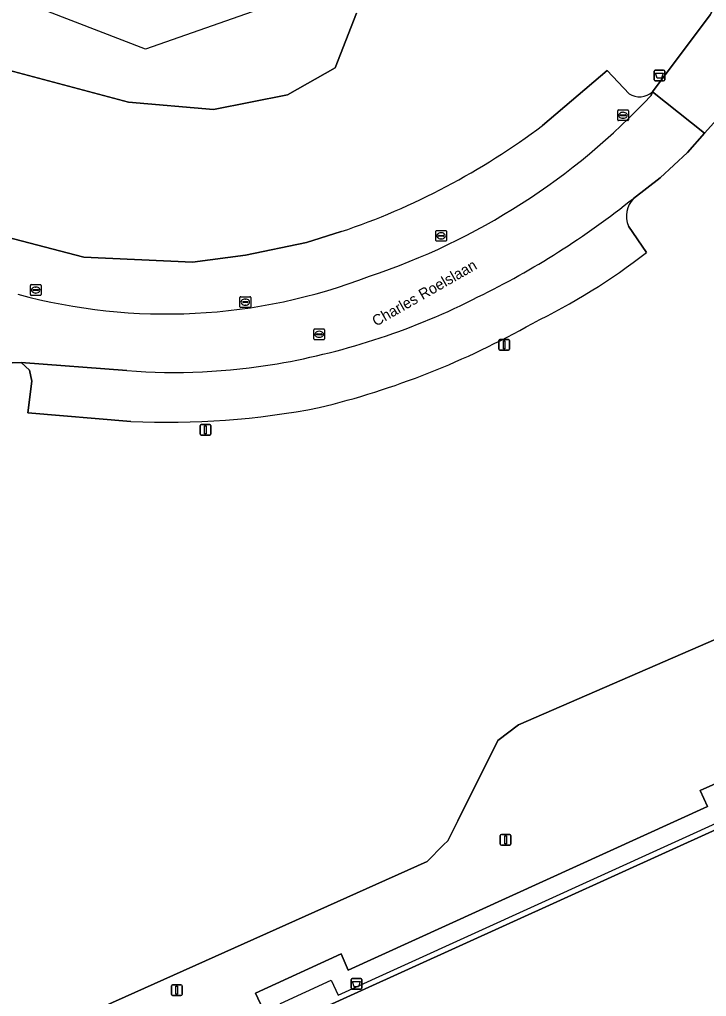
# Model space of a CAD drawing. Extents: x 161090 to 161692, y 379509 to 380907.
# Drawn here: x 161218.4 to 161282.3, y 380030.3 to 380121.1 of the extents above; entities that cross this region are included whole.
import ezdxf

# ---------------------------------------------------------------- set-up
doc = ezdxf.new("R2010")
doc.units = 0
for name, color, linetype in [('IMGEO_Afvalbak', 7, 'Continuous'), ('IMGEO_Groenvoorziening', 7, 'Continuous'), ('IMGEO_Hek', 7, 'Continuous'), ('IMGEO_Kolk', 7, 'Continuous'), ('IMGEO_Lichtmast', 7, 'Continuous'), ('IMGEO_Loofbos', 7, 'Continuous'), ('IMGEO_Openbare_ruimte_label', 7, 'Continuous'), ('IMGEO_Parkeervlak_gesloten', 7, 'Continuous'), ('IMGEO_Rijbaan_lokaal_gesloten', 7, 'Continuous'), ('IMGEO_Rioolput', 7, 'Continuous'), ('IMGEO_Terreindeel_open', 7, 'Continuous'), ('IMGEO_Voetpad_open', 7, 'Continuous'), ('IMGEO_Waterloop', 7, 'Continuous')]:
    doc.layers.add(name, color=color, linetype=linetype)

msp = doc.modelspace()

# ---------------------------------------------------------------- linework, layer by layer
at = {"layer": 'IMGEO_Afvalbak'}
for p, q in [((161277.425, 380115.546), (161277.425, 380116.346)), ((161277.425, 380116.346), (161277.425, 380115.546)), ((161277.525, 380116.446), (161278.315, 380116.446)), ((161278.315, 380116.446), (161277.525, 380116.446)), ((161278.415, 380116.346), (161278.415, 380115.546)), ((161278.415, 380115.546), (161278.415, 380116.346)), ((161278.315, 380115.446), (161277.525, 380115.446)), ((161277.525, 380115.446), (161278.315, 380115.446)), ((161249.255, 380031.115), (161249.255, 380031.915)), ((161249.255, 380031.915), (161249.255, 380031.115)), ((161249.355, 380032.015), (161250.145, 380032.015)), ((161250.145, 380032.015), (161249.355, 380032.015)), ((161250.245, 380031.915), (161250.245, 380031.115)), ((161250.245, 380031.115), (161250.245, 380031.915)), ((161250.145, 380031.015), (161249.355, 380031.015)), ((161249.355, 380031.015), (161250.145, 380031.015))]:
    msp.add_line(p, q, dxfattribs=at)
for points in [[(161277.568, 380116.16), (161278.272, 380116.16), (161278.123, 380115.69), (161277.717, 380115.69), (161277.568, 380116.16)], [(161249.398, 380031.729), (161250.102, 380031.729), (161249.953, 380031.259), (161249.547, 380031.259), (161249.398, 380031.729)]]:
    msp.add_lwpolyline(points, dxfattribs=at)
for centre, start, end in [((161277.525, 380116.346), 90, 180), ((161277.525, 380116.346), 90, 180), ((161278.315, 380116.346), 0, 90), ((161278.315, 380116.346), 360, 90), ((161277.525, 380115.546), 180, 270), ((161277.525, 380115.546), 180, 270), ((161278.315, 380115.546), 270, 0), ((161278.315, 380115.546), 270, 0), ((161249.355, 380031.915), 90, 180), ((161249.355, 380031.915), 90, 180), ((161250.145, 380031.915), 0, 90), ((161250.145, 380031.915), 360, 90), ((161249.355, 380031.115), 180, 270), ((161249.355, 380031.115), 180, 270), ((161250.145, 380031.115), 270, 0), ((161250.145, 380031.115), 270, 0)]:
    msp.add_arc(centre, 0.1, start, end, dxfattribs=at)
at = {"layer": 'IMGEO_Groenvoorziening'}
msp.add_lwpolyline([(161305.516, 380073.263), (161264.808, 380055.587), (161262.89, 380054.125), (161259.172, 380046.687), (161258.233, 380044.807), (161257.86, 380044.434), (161256.315, 380042.888), (161212.115, 380023.104), (161244.332, 379950.948), (161248.71, 379952.968), (161248.207, 379953.948), (161218.695, 380019.077), (161223.462, 380021.221), (161230.069, 380024.187), (161241.037, 380029.206), (161240.363, 380030.654), (161248.318, 380034.301), (161248.967, 380032.793), (161282.396, 380047.991), (161281.717, 380049.48), (161289.948, 380053.183)], dxfattribs=at)
at = {"layer": 'IMGEO_Hek'}
msp.add_lwpolyline([(161282.49, 379981.114), (161272.326, 379976.507), (161272.946, 379975.155), (161268.403, 379973.073), (161267.745, 379974.424), (161245.458, 379964.327), (161243.588, 379968.636), (161221.01, 380018.226), (161243.313, 380028.348), (161242.697, 380029.7), (161247.399, 380031.857), (161248.045, 380030.463), (161284.892, 380047.225), (161284.302, 380048.589), (161288.939, 380050.72), (161289.598, 380049.351), (161311.663, 380059.359), (161336.159, 380005.46), (161313.894, 379995.295), (161314.507, 379993.981), (161309.839, 379991.856), (161309.202, 379993.224), (161299.077, 379988.609)], dxfattribs=at)
at = {"layer": 'IMGEO_Kolk'}
for p, q in [((161274.042, 380111.822), (161274.042, 380112.674)), ((161274.117, 380112.748), (161274.969, 380112.748)), ((161274.344, 380112.291), (161274.742, 380112.291)), ((161274.53, 380112.528), (161274.555, 380112.528)), ((161275.043, 380112.674), (161275.043, 380111.822)), ((161274.969, 380111.748), (161274.117, 380111.748)), ((161274.301, 380112.242), (161274.301, 380112.254)), ((161274.739, 380112.205), (161274.341, 380112.205)), ((161274.553, 380111.968), (161274.528, 380111.968)), ((161274.785, 380112.254), (161274.785, 380112.242)), ((161257.126, 380100.616), (161257.126, 380101.468)), ((161257.201, 380101.542), (161258.053, 380101.542)), ((161258.127, 380101.468), (161258.127, 380100.616)), ((161258.053, 380100.542), (161257.201, 380100.542)), ((161257.385, 380101.036), (161257.385, 380101.048)), ((161257.823, 380100.999), (161257.425, 380100.999)), ((161257.428, 380101.085), (161257.826, 380101.085)), ((161257.637, 380100.762), (161257.612, 380100.762)), ((161257.614, 380101.322), (161257.639, 380101.322)), ((161257.869, 380101.048), (161257.869, 380101.036)), ((161219.439, 380095.581), (161219.439, 380096.433)), ((161219.514, 380096.507), (161220.366, 380096.507)), ((161219.698, 380096.001), (161219.698, 380096.013)), ((161220.136, 380095.964), (161219.738, 380095.964)), ((161219.741, 380096.05), (161220.139, 380096.05)), ((161219.927, 380096.287), (161219.952, 380096.287)), ((161220.182, 380096.013), (161220.182, 380096.001)), ((161220.44, 380096.433), (161220.44, 380095.581)), ((161220.366, 380095.507), (161219.514, 380095.507)), ((161219.95, 380095.727), (161219.925, 380095.727)), ((161238.918, 380094.458), (161238.918, 380095.31)), ((161238.993, 380095.384), (161239.845, 380095.384)), ((161239.406, 380095.164), (161239.431, 380095.164)), ((161239.919, 380095.31), (161239.919, 380094.458)), ((161239.845, 380094.384), (161238.993, 380094.384)), ((161239.177, 380094.878), (161239.177, 380094.89)), ((161239.615, 380094.841), (161239.217, 380094.841)), ((161239.22, 380094.927), (161239.618, 380094.927)), ((161239.429, 380094.604), (161239.404, 380094.604)), ((161239.661, 380094.89), (161239.661, 380094.878))]:
    msp.add_line(p, q, dxfattribs=at)
for points in [[(161274.042, 380111.822), (161274.042, 380112.674)], [(161274.117, 380112.748), (161274.969, 380112.748)], [(161275.043, 380112.674), (161275.043, 380111.822)], [(161274.969, 380111.748), (161274.117, 380111.748)], [(161257.126, 380100.616), (161257.126, 380101.468)], [(161257.201, 380101.542), (161258.053, 380101.542)], [(161258.127, 380101.468), (161258.127, 380100.616)], [(161258.053, 380100.542), (161257.201, 380100.542)], [(161219.439, 380095.581), (161219.439, 380096.433)], [(161219.514, 380096.507), (161220.366, 380096.507)], [(161220.44, 380096.433), (161220.44, 380095.581)], [(161220.366, 380095.507), (161219.514, 380095.507)], [(161238.918, 380094.458), (161238.918, 380095.31)], [(161238.993, 380095.384), (161239.845, 380095.384)], [(161239.919, 380095.31), (161239.919, 380094.458)], [(161239.845, 380094.384), (161238.993, 380094.384)]]:
    msp.add_lwpolyline(points, dxfattribs=at)
for centre, radius, start, end in [((161274.119, 380112.672), 0.0765, 91.55205, 178.44795), ((161274.119, 380112.672), 0.0765, 91.55205, 178.44795), ((161274.341, 380112.251), 0.0403, 85.87752, 175.75265), ((161274.746, 380112.253), 0.0386, 1.73085, 96.63898), ((161274.967, 380112.672), 0.0765, 1.55205, 88.44795), ((161274.967, 380112.672), 0.0765, 1.55205, 88.44795), ((161274.119, 380111.824), 0.0765, 181.55205, 268.44795), ((161274.119, 380111.824), 0.0765, 181.55205, 268.44795), ((161274.338, 380112.241), 0.0366, 178.93798, 274.71019), ((161274.742, 380112.248), 0.043, 264.86636, 352.45326), ((161274.967, 380111.824), 0.0765, 271.55205, 358.44795), ((161274.967, 380111.824), 0.0765, 271.55205, 358.44795), ((161257.203, 380101.466), 0.0765, 91.55205, 178.44795), ((161257.203, 380101.466), 0.0765, 91.55205, 178.44795), ((161258.051, 380101.466), 0.0765, 1.55205, 88.44795), ((161258.051, 380101.466), 0.0765, 1.55205, 88.44795), ((161257.203, 380100.618), 0.0765, 181.55205, 268.44795), ((161257.203, 380100.618), 0.0765, 181.55205, 268.44795), ((161257.425, 380101.045), 0.0403, 85.87752, 175.75265), ((161257.422, 380101.035), 0.0366, 178.93798, 274.71019), ((161257.826, 380101.042), 0.043, 264.86636, 352.45326), ((161257.83, 380101.047), 0.0386, 1.73085, 96.63898), ((161258.051, 380100.618), 0.0765, 271.55205, 358.44795), ((161258.051, 380100.618), 0.0765, 271.55205, 358.44795), ((161219.516, 380096.431), 0.0765, 91.55205, 178.44795), ((161219.516, 380096.431), 0.0765, 91.55205, 178.44795), ((161219.738, 380096.01), 0.0403, 85.87752, 175.75265), ((161219.735, 380096), 0.0366, 178.93798, 274.71019), ((161220.139, 380096.007), 0.043, 264.86636, 352.45326), ((161220.143, 380096.012), 0.0386, 1.73085, 96.63898), ((161220.364, 380096.431), 0.0765, 1.55205, 88.44795), ((161220.364, 380096.431), 0.0765, 1.55205, 88.44795), ((161219.516, 380095.583), 0.0765, 181.55205, 268.44795), ((161219.516, 380095.583), 0.0765, 181.55205, 268.44795), ((161220.364, 380095.583), 0.0765, 271.55205, 358.44795), ((161220.364, 380095.583), 0.0765, 271.55205, 358.44795), ((161238.995, 380095.308), 0.0765, 91.55205, 178.44795), ((161238.995, 380095.308), 0.0765, 91.55205, 178.44795), ((161239.843, 380095.308), 0.0765, 1.55205, 88.44795), ((161239.843, 380095.308), 0.0765, 1.55205, 88.44795), ((161238.995, 380094.46), 0.0765, 181.55205, 268.44795), ((161238.995, 380094.46), 0.0765, 181.55205, 268.44795), ((161239.217, 380094.887), 0.0403, 85.87752, 175.75265), ((161239.214, 380094.877), 0.0366, 178.93798, 274.71019), ((161239.618, 380094.884), 0.043, 264.86636, 352.45326), ((161239.622, 380094.889), 0.0386, 1.73085, 96.63898), ((161239.843, 380094.46), 0.0765, 271.55205, 358.44795), ((161239.843, 380094.46), 0.0765, 271.55205, 358.44795)]:
    msp.add_arc(centre, radius, start, end, dxfattribs=at)
for centre, major_axis, ratio, start_param, end_param in [((161274.529, 380112.248), (-0.387, 0.002), 0.722429, 4.712389, 7.853982), ((161274.554, 380112.248), (-0.39, 0.002), 0.717154, 1.570796, 4.712389), ((161257.613, 380101.042), (-0.387, 0.002), 0.722429, 4.712389, 7.853982), ((161257.638, 380101.042), (-0.39, 0.002), 0.717154, 1.570796, 4.712389), ((161219.926, 380096.007), (-0.387, 0.002), 0.722429, 4.712389, 7.853982), ((161219.951, 380096.007), (-0.39, 0.002), 0.717154, 1.570796, 4.712389), ((161239.405, 380094.884), (-0.387, 0.002), 0.722429, 4.712389, 7.853982), ((161239.43, 380094.884), (-0.39, 0.002), 0.717154, 1.570796, 4.712389)]:
    msp.add_ellipse(centre, major_axis=major_axis, ratio=ratio, start_param=start_param, end_param=end_param, dxfattribs=at)
at = {"layer": 'IMGEO_Lichtmast'}
for p, q in [((161263.093, 380091.406), (161263.883, 380091.406)), ((161263.883, 380091.406), (161263.093, 380091.406)), ((161262.993, 380090.506), (161262.993, 380091.306)), ((161262.993, 380091.306), (161262.993, 380090.506)), ((161263.983, 380091.306), (161263.983, 380090.506)), ((161263.983, 380090.506), (161263.983, 380091.306)), ((161263.883, 380090.406), (161263.093, 380090.406)), ((161263.093, 380090.406), (161263.883, 380090.406)), ((161235.219, 380082.608), (161235.219, 380083.408)), ((161235.219, 380083.408), (161235.219, 380082.608)), ((161235.319, 380083.508), (161236.109, 380083.508)), ((161236.109, 380083.508), (161235.319, 380083.508)), ((161236.209, 380083.408), (161236.209, 380082.608)), ((161236.209, 380082.608), (161236.209, 380083.408)), ((161236.109, 380082.508), (161235.319, 380082.508)), ((161235.319, 380082.508), (161236.109, 380082.508)), ((161263.127, 380044.505), (161263.127, 380045.305)), ((161263.127, 380045.305), (161263.127, 380044.505)), ((161263.227, 380045.405), (161264.017, 380045.405)), ((161264.017, 380045.405), (161263.227, 380045.405)), ((161264.117, 380045.305), (161264.117, 380044.505)), ((161264.117, 380044.505), (161264.117, 380045.305)), ((161264.017, 380044.405), (161263.227, 380044.405)), ((161263.227, 380044.405), (161264.017, 380044.405)), ((161232.546, 380030.534), (161232.546, 380031.334)), ((161232.546, 380031.334), (161232.546, 380030.534)), ((161232.646, 380031.434), (161233.436, 380031.434)), ((161233.436, 380031.434), (161232.646, 380031.434)), ((161233.536, 380031.334), (161233.536, 380030.534)), ((161233.536, 380030.534), (161233.536, 380031.334)), ((161233.436, 380030.434), (161232.646, 380030.434)), ((161232.646, 380030.434), (161233.436, 380030.434))]:
    msp.add_line(p, q, dxfattribs=at)
for points in [[(161263.413, 380091.281), (161263.563, 380091.281), (161263.563, 380090.531), (161263.413, 380090.531), (161263.413, 380091.281)], [(161235.639, 380083.383), (161235.789, 380083.383), (161235.789, 380082.633), (161235.639, 380082.633), (161235.639, 380083.383)], [(161263.547, 380045.28), (161263.697, 380045.28), (161263.697, 380044.53), (161263.547, 380044.53), (161263.547, 380045.28)], [(161232.966, 380031.309), (161233.116, 380031.309), (161233.116, 380030.559), (161232.966, 380030.559), (161232.966, 380031.309)]]:
    msp.add_lwpolyline(points, dxfattribs=at)
for centre, start, end in [((161263.093, 380091.306), 90, 180), ((161263.093, 380091.306), 90, 180), ((161263.883, 380091.306), 0, 90), ((161263.883, 380091.306), 360, 90), ((161263.093, 380090.506), 180, 270), ((161263.093, 380090.506), 180, 270), ((161263.883, 380090.506), 270, 0), ((161263.883, 380090.506), 270, 0), ((161235.319, 380083.408), 90, 180), ((161235.319, 380083.408), 90, 180), ((161236.109, 380083.408), 0, 90), ((161236.109, 380083.408), 360, 90), ((161235.319, 380082.608), 180, 270), ((161235.319, 380082.608), 180, 270), ((161236.109, 380082.608), 270, 0), ((161236.109, 380082.608), 270, 0), ((161263.227, 380045.305), 90, 180), ((161263.227, 380045.305), 90, 180), ((161264.017, 380045.305), 0, 90), ((161264.017, 380045.305), 360, 90), ((161263.227, 380044.505), 180, 270), ((161263.227, 380044.505), 180, 270), ((161264.017, 380044.505), 270, 0), ((161264.017, 380044.505), 270, 0), ((161232.646, 380031.334), 90, 180), ((161232.646, 380031.334), 90, 180), ((161233.436, 380031.334), 0, 90), ((161233.436, 380031.334), 360, 90), ((161232.646, 380030.534), 180, 270), ((161232.646, 380030.534), 180, 270), ((161233.436, 380030.534), 270, 0), ((161233.436, 380030.534), 270, 0)]:
    msp.add_arc(centre, 0.1, start, end, dxfattribs=at)
at = {"layer": 'IMGEO_Loofbos'}
for points in [[(161277.27, 380114.427), (161282.644, 380121.57), (161285.114, 380126.208), (161288.728, 380134.19), (161288.702, 380135.225)], [(161249.77, 380121.723), (161247.767, 380116.659), (161243.343, 380114.139), (161236.467, 380112.791), (161228.567, 380113.465), (161216.431, 380116.702), (161207.098, 380120.68), (161201.052, 380123.512)], [(161256.315, 380042.888), (161257.86, 380044.434), (161258.233, 380044.807), (161259.172, 380046.687), (161262.89, 380054.125), (161264.808, 380055.587), (161305.516, 380073.263), (161306.926, 380074.038), (161295.641, 380101.102), (161292.779, 380118.588), (161288.647, 380119.629), (161286.801, 380116.69), (161284.361, 380113.106), (161282.126, 380110.59), (161280.535, 380108.799), (161278.005, 380106.449), (161275.496, 380104.524)], [(161267.061, 380111.307), (161273.075, 380116.41), (161275.095, 380114.256)], [(161145.106, 379983.352), (161142.114, 379984.249), (161146.161, 380000), (161174.92, 380111.917), (161179.667, 380110.715), (161185.279, 380109.252), (161224.417, 380099.047), (161234.496, 380098.584), (161239.445, 380099.25), (161245.106, 380100.414), (161248.326, 380101.431)], [(161275.041, 380101.945), (161276.712, 380099.498)], [(161228.79, 380083.796), (161219.203, 380084.584), (161219.566, 380087.532), (161219.355, 380088.565), (161218.585, 380089.286), (161216.916, 380089.198), (161215.297, 380088.786), (161213.844, 380087.738), (161212.707, 380086.355)], [(161236.661, 379947.409), (161244.332, 379950.948), (161212.115, 380023.104), (161256.315, 380042.888)]]:
    msp.add_lwpolyline(points, dxfattribs=at)
for centre, radius, start, end in [((161276.073, 380115.732), 1.771, 236.46737, 312.5234), ((161227.072, 380164.458), 66.514, 288.63484, 306.95633), ((161277.327, 380102.871), 2.467, 137.93564, 202.05347), ((161240.405, 380146.102), 59.077, 295.79028, 307.92081), ((161228.32, 380159.582), 76.637, 283.56895, 299.5433), ((161232.245, 380156.486), 72.772, 267.27842, 281.13555)]:
    msp.add_arc(centre, radius, start, end, dxfattribs=at)
at = {"layer": 'IMGEO_Parkeervlak_gesloten'}
for points in [[(161275.095, 380114.256), (161273.075, 380116.41), (161267.061, 380111.307)], [(161275.496, 380104.524), (161278.005, 380106.449), (161280.535, 380108.799), (161282.126, 380110.59), (161277.27, 380114.427), (161277.14, 380114.078)], [(161277.14, 380114.078), (161277.27, 380114.427)], [(161248.326, 380101.431), (161245.106, 380100.414), (161239.445, 380099.25), (161234.496, 380098.584), (161224.417, 380099.047), (161185.279, 380109.252)], [(161276.712, 380099.498), (161275.041, 380101.945)], [(161212.707, 380086.355), (161213.844, 380087.738), (161215.297, 380088.786), (161216.916, 380089.198), (161218.585, 380089.286), (161228.417, 380088.513)], [(161228.417, 380088.513), (161218.585, 380089.286), (161219.355, 380088.565), (161219.566, 380087.532), (161219.203, 380084.584), (161228.79, 380083.796)]]:
    msp.add_lwpolyline(points, dxfattribs=at)
for centre, radius, start, end in [((161276.073, 380115.732), 1.771, 236.46737, 312.5234), ((161231.031, 380157.156), 63.101, 288.41006, 316.94684), ((161231.031, 380157.156), 63.101, 288.41006, 316.94684), ((161227.072, 380164.458), 66.514, 288.63484, 306.95633), ((161226.837, 380165.272), 77.834, 296.07535, 308.69442), ((161226.837, 380165.272), 77.834, 296.07535, 308.69442), ((161277.327, 380102.871), 2.467, 137.93564, 202.05347), ((161240.405, 380146.102), 59.077, 295.79028, 307.92081), ((161232.053, 380146.531), 52.751, 254.85396, 291.00215), ((161232.053, 380146.531), 52.751, 254.85396, 291.00215), ((161231.211, 380153.933), 65.735, 279.7952, 296.99543), ((161231.211, 380153.933), 65.735, 279.7952, 296.99543), ((161228.32, 380159.582), 76.637, 283.56895, 299.5433), ((161232.782, 380145.764), 57.417, 265.63958, 279.63658), ((161232.782, 380145.764), 57.417, 265.63958, 279.63658), ((161232.245, 380156.486), 72.772, 267.27842, 281.13555)]:
    msp.add_arc(centre, radius, start, end, dxfattribs=at)
at = {"layer": 'IMGEO_Rijbaan_lokaal_gesloten'}
msp.add_lwpolyline([(161305.937, 380183.804), (161297.167, 380183.699), (161296.972, 380182.47), (161293.197, 380157.657), (161291.529, 380146.508), (161291.111, 380143.774), (161291.078, 380143.558), (161290.475, 380140.515), (161288.728, 380134.19), (161285.114, 380126.208), (161282.644, 380121.57), (161277.27, 380114.427), (161282.126, 380110.59), (161284.361, 380113.106), (161286.801, 380116.69), (161288.647, 380119.629), (161289.503, 380120.993), (161289.903, 380121.63)], dxfattribs=at)
at = {"layer": 'IMGEO_Rioolput'}
for p, q in [((161245.785, 380091.464), (161245.785, 380092.316)), ((161245.86, 380092.39), (161246.712, 380092.39)), ((161246.786, 380092.316), (161246.786, 380091.464)), ((161246.044, 380091.884), (161246.044, 380091.896)), ((161246.482, 380091.847), (161246.084, 380091.847)), ((161246.087, 380091.933), (161246.485, 380091.933)), ((161246.296, 380091.61), (161246.271, 380091.61)), ((161246.273, 380092.17), (161246.298, 380092.17)), ((161246.528, 380091.896), (161246.528, 380091.884)), ((161246.712, 380091.39), (161245.86, 380091.39))]:
    msp.add_line(p, q, dxfattribs=at)
for points in [[(161245.785, 380091.464), (161245.785, 380092.316)], [(161245.86, 380092.39), (161246.712, 380092.39)], [(161246.786, 380092.316), (161246.786, 380091.464)], [(161246.712, 380091.39), (161245.86, 380091.39)]]:
    msp.add_lwpolyline(points, dxfattribs=at)
for centre, radius, start, end in [((161245.862, 380092.314), 0.0765, 91.55205, 178.44795), ((161245.862, 380092.314), 0.0765, 91.55205, 178.44795), ((161246.71, 380092.314), 0.0765, 1.55205, 88.44795), ((161246.71, 380092.314), 0.0765, 1.55205, 88.44795), ((161245.862, 380091.466), 0.0765, 181.55205, 268.44795), ((161245.862, 380091.466), 0.0765, 181.55205, 268.44795), ((161246.084, 380091.893), 0.0403, 85.87752, 175.75265), ((161246.081, 380091.883), 0.0366, 178.93798, 274.71019), ((161246.485, 380091.89), 0.043, 264.86636, 352.45326), ((161246.489, 380091.895), 0.0386, 1.73085, 96.63898), ((161246.71, 380091.466), 0.0765, 271.55205, 358.44795), ((161246.71, 380091.466), 0.0765, 271.55205, 358.44795)]:
    msp.add_arc(centre, radius, start, end, dxfattribs=at)
for centre, major_axis, ratio, start_param, end_param in [((161246.272, 380091.89), (-0.387, 0.002), 0.722429, 4.712389, 7.853982), ((161246.297, 380091.89), (-0.39, 0.002), 0.717154, 1.570796, 4.712389)]:
    msp.add_ellipse(centre, major_axis=major_axis, ratio=ratio, start_param=start_param, end_param=end_param, dxfattribs=at)
at = {"layer": 'IMGEO_Terreindeel_open'}
msp.add_lwpolyline([(161311.457, 380058.707), (161231.045, 380022.212), (161221.64, 380017.991), (161243.977, 379968.805), (161245.706, 379964.978), (161335.517, 380005.692)], close=True, dxfattribs=at)
at = {"layer": 'IMGEO_Voetpad_open'}
msp.add_lwpolyline([(161231.045, 380022.212), (161311.457, 380058.707), (161335.517, 380005.692), (161245.706, 379964.978), (161243.977, 379968.805), (161221.64, 380017.991)], close=True, dxfattribs=at)
msp.add_lwpolyline([(161289.948, 380053.183), (161281.717, 380049.48), (161282.396, 380047.991), (161248.967, 380032.793), (161248.318, 380034.301), (161240.363, 380030.654), (161241.037, 380029.206), (161230.069, 380024.187), (161223.462, 380021.221), (161218.695, 380019.077), (161248.207, 379953.948), (161249.827, 379954.657), (161247.6, 379959.725), (161249.331, 379964.203), (161266.77, 379972.11), (161267.409, 379970.737), (161316.845, 379993.15)], dxfattribs=at)
at = {"layer": 'IMGEO_Waterloop'}
for points in [[(161241.929, 380122.519), (161230.138, 380118.401), (161205.435, 380127.948)], [(161201.052, 380123.512), (161207.098, 380120.68), (161216.431, 380116.702), (161228.567, 380113.465), (161236.467, 380112.791), (161243.343, 380114.139), (161247.767, 380116.659), (161249.77, 380121.723)]]:
    msp.add_lwpolyline(points, dxfattribs=at)

# ---------------------------------------------------------------- texts
at = {"layer": 'IMGEO_Openbare_ruimte_label'}
msp.add_text('Charles Roelslaan', height=1, rotation=29.79462, dxfattribs=at).set_placement((161251.572, 380092.591))

doc.saveas('drawing.dxf')
